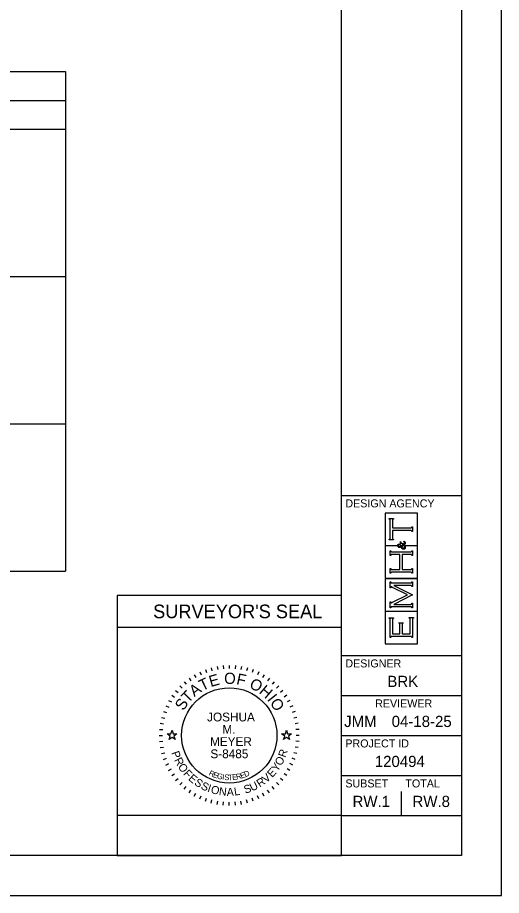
# Model space of a CAD drawing. Extents: x 0 to 34, y 0 to 22.
# Drawn here: x 27.95 to 34, y 0 to 10.97 of the extents above; entities that cross this region are included whole.
import ezdxf

# ---------------------------------------------------------------- set-up
doc = ezdxf.new("R2010")
doc.units = 0
for name, color, linetype in [('Default', 7, 'Continuous'), ('SH_Border', 7, 'Continuous'), ('SH_Cut_Line', 7, 'Continuous'), ('SH_Data', 7, 'Continuous')]:
    doc.layers.add(name, color=color, linetype=linetype)

msp = doc.modelspace()

# ---------------------------------------------------------------- linework, layer by layer
at = {"layer": 'Default'}
for points in [[(29.824, 2.02), (29.871, 2.02), (29.885, 2.065), (29.899, 2.02), (29.946, 2.02), (29.908, 1.992), (29.923, 1.948), (29.885, 1.975), (29.847, 1.948), (29.862, 1.992)], [(31.254, 2.02), (31.301, 2.02), (31.315, 2.065), (31.329, 2.02), (31.376, 2.02), (31.338, 1.992), (31.353, 1.948), (31.315, 1.975), (31.277, 1.948), (31.292, 1.992)]]:
    msp.add_lwpolyline(points, close=True, dxfattribs=at)
at = {"layer": 'SH_Border'}
for p, q in [((32, 0.5), (32, 21.5)), ((32, 5), (33.5, 5)), ((32, 3), (33.5, 3)), ((32, 2.5), (33.5, 2.5)), ((32, 2), (33.5, 2)), ((32, 1.5), (33.5, 1.5)), ((32, 1), (33.5, 1))]:
    msp.add_line(p, q, dxfattribs=at)
msp.add_lwpolyline([(1.5, 21.5), (33.5, 21.5), (33.5, 0.5), (1.5, 0.5)], close=True, dxfattribs=at)
at = {"layer": 'SH_Cut_Line'}
msp.add_lwpolyline([(0, 0), (34, 0), (34, 22), (0, 22)], close=True, dxfattribs=at)
at = {"layer": 'SH_Data'}
for p, q in [((16.868, 10.297), (28.553, 10.297)), ((28.553, 10.297), (28.553, 4.053)), ((16.868, 9.937), (28.553, 9.937)), ((16.868, 9.577), (28.553, 9.577)), ((16.868, 7.736), (28.553, 7.736)), ((16.868, 5.894), (28.553, 5.894)), ((32.952, 4.779), (32.547, 4.779)), ((32.547, 4.779), (32.547, 4.375)), ((32.952, 4.375), (32.952, 4.779)), ((32.598, 4.704), (32.598, 4.711)), ((32.598, 4.711), (32.65, 4.711)), ((32.603, 4.703), (32.598, 4.704)), ((32.606, 4.701), (32.603, 4.703)), ((32.608, 4.699), (32.606, 4.701)), ((32.61, 4.696), (32.608, 4.699)), ((32.611, 4.692), (32.61, 4.696)), ((32.611, 4.687), (32.611, 4.692)), ((32.611, 4.468), (32.611, 4.687)), ((32.638, 4.696), (32.637, 4.692)), ((32.637, 4.692), (32.637, 4.687)), ((32.637, 4.687), (32.637, 4.593)), ((32.64, 4.699), (32.638, 4.696)), ((32.642, 4.701), (32.64, 4.699)), ((32.645, 4.703), (32.642, 4.701)), ((32.65, 4.704), (32.645, 4.703)), ((32.65, 4.711), (32.65, 4.704)), ((32.637, 4.593), (32.864, 4.593)), ((32.864, 4.561), (32.637, 4.561)), ((32.637, 4.561), (32.637, 4.468)), ((32.864, 4.593), (32.869, 4.593)), ((32.87, 4.561), (32.864, 4.561)), ((32.869, 4.593), (32.873, 4.594)), ((32.874, 4.56), (32.87, 4.561)), ((32.873, 4.594), (32.876, 4.596)), ((32.876, 4.559), (32.874, 4.56)), ((32.876, 4.596), (32.878, 4.597)), ((32.878, 4.557), (32.876, 4.559)), ((32.878, 4.597), (32.88, 4.601)), ((32.88, 4.553), (32.878, 4.557)), ((32.88, 4.601), (32.881, 4.606)), ((32.881, 4.548), (32.88, 4.553)), ((32.881, 4.606), (32.888, 4.606)), ((32.888, 4.548), (32.881, 4.548)), ((32.888, 4.606), (32.888, 4.548)), ((32.598, 4.45), (32.603, 4.451)), ((32.598, 4.444), (32.598, 4.45)), ((32.65, 4.444), (32.598, 4.444)), ((32.603, 4.451), (32.606, 4.453)), ((32.606, 4.453), (32.608, 4.455)), ((32.608, 4.455), (32.61, 4.458)), ((32.61, 4.458), (32.611, 4.462)), ((32.611, 4.462), (32.611, 4.468)), ((32.637, 4.468), (32.637, 4.462)), ((32.637, 4.462), (32.638, 4.458)), ((32.638, 4.458), (32.64, 4.455)), ((32.64, 4.455), (32.642, 4.453)), ((32.642, 4.453), (32.645, 4.451)), ((32.645, 4.451), (32.65, 4.45)), ((32.65, 4.45), (32.65, 4.444)), ((32.708, 4.387), (32.711, 4.39)), ((32.711, 4.39), (32.715, 4.392)), ((32.715, 4.392), (32.72, 4.392)), ((32.72, 4.392), (32.725, 4.392)), ((32.725, 4.392), (32.729, 4.39)), ((32.729, 4.39), (32.732, 4.387)), ((32.738, 4.393), (32.738, 4.422)), ((32.738, 4.422), (32.741, 4.422)), ((32.741, 4.393), (32.738, 4.393)), ((32.741, 4.422), (32.741, 4.418)), ((32.741, 4.418), (32.742, 4.415)), ((32.742, 4.396), (32.741, 4.395)), ((32.741, 4.395), (32.741, 4.393)), ((32.742, 4.415), (32.743, 4.413)), ((32.743, 4.397), (32.742, 4.396)), ((32.743, 4.413), (32.745, 4.411)), ((32.745, 4.399), (32.743, 4.397)), ((32.745, 4.411), (32.749, 4.408)), ((32.746, 4.399), (32.745, 4.399)), ((32.748, 4.399), (32.746, 4.399)), ((32.755, 4.399), (32.748, 4.399)), ((32.749, 4.408), (32.756, 4.404)), ((32.763, 4.395), (32.755, 4.399)), ((32.756, 4.404), (32.763, 4.4)), ((32.763, 4.4), (32.77, 4.396)), ((32.772, 4.387), (32.763, 4.395)), ((32.77, 4.396), (32.776, 4.391)), ((32.776, 4.391), (32.781, 4.395)), ((32.779, 4.423), (32.781, 4.426)), ((32.782, 4.422), (32.779, 4.423)), ((32.781, 4.426), (32.787, 4.424)), ((32.781, 4.395), (32.784, 4.398)), ((32.785, 4.421), (32.782, 4.422)), ((32.784, 4.398), (32.786, 4.401)), ((32.786, 4.419), (32.785, 4.421)), ((32.788, 4.417), (32.786, 4.419)), ((32.786, 4.401), (32.788, 4.404)), ((32.787, 4.424), (32.792, 4.421)), ((32.789, 4.414), (32.788, 4.417)), ((32.788, 4.404), (32.789, 4.408)), ((32.789, 4.411), (32.789, 4.414)), ((32.789, 4.408), (32.789, 4.411)), ((32.794, 4.39), (32.791, 4.386)), ((32.792, 4.421), (32.795, 4.418)), ((32.796, 4.394), (32.794, 4.39)), ((32.795, 4.418), (32.798, 4.414)), ((32.798, 4.397), (32.796, 4.394)), ((32.798, 4.414), (32.799, 4.41)), ((32.799, 4.401), (32.798, 4.397)), ((32.799, 4.41), (32.799, 4.405)), ((32.799, 4.405), (32.799, 4.401)), ((32.547, 4.375), (32.696, 4.375)), ((32.696, 4.369), (32.547, 4.369)), ((32.547, 4.369), (32.547, 3.965)), ((32.611, 4.249), (32.611, 4.307)), ((32.611, 4.307), (32.617, 4.307)), ((32.617, 4.307), (32.619, 4.302)), ((32.619, 4.302), (32.62, 4.298)), ((32.62, 4.298), (32.623, 4.297)), ((32.623, 4.297), (32.625, 4.295)), ((32.625, 4.295), (32.629, 4.294)), ((32.629, 4.294), (32.635, 4.294)), ((32.635, 4.294), (32.864, 4.294)), ((32.696, 4.375), (32.696, 4.369)), ((32.703, 4.379), (32.705, 4.383)), ((32.703, 4.373), (32.703, 4.379)), ((32.703, 4.368), (32.703, 4.373)), ((32.705, 4.363), (32.703, 4.368)), ((32.705, 4.383), (32.708, 4.387)), ((32.708, 4.358), (32.705, 4.363)), ((32.709, 4.379), (32.708, 4.376)), ((32.708, 4.376), (32.708, 4.373)), ((32.708, 4.373), (32.708, 4.369)), ((32.708, 4.369), (32.71, 4.366)), ((32.712, 4.353), (32.708, 4.358)), ((32.712, 4.381), (32.709, 4.379)), ((32.71, 4.366), (32.712, 4.364)), ((32.714, 4.383), (32.712, 4.381)), ((32.712, 4.364), (32.715, 4.362)), ((32.718, 4.35), (32.712, 4.353)), ((32.716, 4.384), (32.714, 4.383)), ((32.715, 4.362), (32.718, 4.361)), ((32.72, 4.384), (32.716, 4.384)), ((32.718, 4.361), (32.721, 4.361)), ((32.726, 4.35), (32.718, 4.35)), ((32.724, 4.384), (32.72, 4.384)), ((32.721, 4.361), (32.723, 4.361)), ((32.723, 4.361), (32.725, 4.362)), ((32.728, 4.382), (32.724, 4.384)), ((32.725, 4.362), (32.728, 4.362)), ((32.729, 4.35), (32.726, 4.35)), ((32.731, 4.38), (32.728, 4.382)), ((32.728, 4.362), (32.731, 4.363)), ((32.731, 4.35), (32.729, 4.35)), ((32.734, 4.377), (32.731, 4.38)), ((32.731, 4.363), (32.735, 4.365)), ((32.734, 4.351), (32.731, 4.35)), ((32.732, 4.387), (32.736, 4.383)), ((32.737, 4.372), (32.734, 4.377)), ((32.737, 4.352), (32.734, 4.351)), ((32.735, 4.365), (32.74, 4.367)), ((32.736, 4.383), (32.74, 4.378)), ((32.74, 4.367), (32.737, 4.372)), ((32.741, 4.353), (32.737, 4.352)), ((32.74, 4.378), (32.744, 4.369)), ((32.746, 4.355), (32.741, 4.353)), ((32.744, 4.369), (32.754, 4.375)), ((32.752, 4.344), (32.746, 4.355)), ((32.756, 4.36), (32.751, 4.357)), ((32.751, 4.357), (32.754, 4.352)), ((32.757, 4.337), (32.752, 4.344)), ((32.754, 4.375), (32.764, 4.381)), ((32.754, 4.352), (32.757, 4.348)), ((32.761, 4.363), (32.756, 4.36)), ((32.757, 4.348), (32.761, 4.345)), ((32.763, 4.333), (32.757, 4.337)), ((32.764, 4.365), (32.761, 4.363)), ((32.761, 4.345), (32.765, 4.343)), ((32.768, 4.329), (32.763, 4.333)), ((32.764, 4.381), (32.772, 4.387)), ((32.768, 4.367), (32.764, 4.365)), ((32.765, 4.343), (32.769, 4.341)), ((32.774, 4.372), (32.768, 4.367)), ((32.774, 4.327), (32.768, 4.329)), ((32.769, 4.341), (32.773, 4.341)), ((32.773, 4.341), (32.778, 4.341)), ((32.782, 4.378), (32.774, 4.372)), ((32.779, 4.327), (32.774, 4.327)), ((32.778, 4.341), (32.782, 4.343)), ((32.785, 4.327), (32.779, 4.327)), ((32.786, 4.373), (32.782, 4.378)), ((32.782, 4.343), (32.786, 4.346)), ((32.79, 4.329), (32.785, 4.327)), ((32.791, 4.386), (32.786, 4.381)), ((32.786, 4.381), (32.791, 4.376)), ((32.788, 4.369), (32.786, 4.373)), ((32.786, 4.346), (32.789, 4.349)), ((32.79, 4.367), (32.788, 4.369)), ((32.789, 4.349), (32.791, 4.353)), ((32.791, 4.364), (32.79, 4.367)), ((32.793, 4.334), (32.79, 4.329)), ((32.791, 4.376), (32.795, 4.37)), ((32.791, 4.361), (32.791, 4.364)), ((32.791, 4.359), (32.791, 4.361)), ((32.791, 4.353), (32.791, 4.359)), ((32.797, 4.338), (32.793, 4.334)), ((32.795, 4.37), (32.797, 4.366)), ((32.797, 4.366), (32.798, 4.361)), ((32.799, 4.344), (32.797, 4.338)), ((32.798, 4.361), (32.799, 4.357)), ((32.803, 4.369), (32.799, 4.375)), ((32.799, 4.375), (32.952, 4.375)), ((32.799, 4.357), (32.799, 4.352)), ((32.799, 4.352), (32.799, 4.344)), ((32.952, 4.369), (32.803, 4.369)), ((32.864, 4.294), (32.869, 4.294)), ((32.869, 4.294), (32.873, 4.295)), ((32.873, 4.295), (32.876, 4.297)), ((32.876, 4.297), (32.878, 4.298)), ((32.878, 4.298), (32.88, 4.302)), ((32.88, 4.302), (32.881, 4.307)), ((32.881, 4.307), (32.888, 4.307)), ((32.888, 4.307), (32.888, 4.249)), ((32.952, 3.965), (32.952, 4.369)), ((32.617, 4.249), (32.611, 4.249)), ((32.618, 4.254), (32.617, 4.249)), ((32.62, 4.258), (32.618, 4.254)), ((32.623, 4.26), (32.62, 4.258)), ((32.625, 4.261), (32.623, 4.26)), ((32.629, 4.262), (32.625, 4.261)), ((32.635, 4.262), (32.629, 4.262)), ((32.732, 4.262), (32.635, 4.262)), ((32.732, 4.072), (32.732, 4.262)), ((32.864, 4.262), (32.759, 4.262)), ((32.759, 4.262), (32.759, 4.072)), ((32.87, 4.262), (32.864, 4.262)), ((32.874, 4.261), (32.87, 4.262)), ((32.876, 4.26), (32.874, 4.261)), ((32.878, 4.258), (32.876, 4.26)), ((32.88, 4.254), (32.878, 4.258)), ((32.881, 4.249), (32.88, 4.254)), ((32.888, 4.249), (32.881, 4.249)), ((32.611, 4.027), (32.611, 4.085)), ((32.611, 4.085), (32.617, 4.085)), ((32.617, 4.085), (32.619, 4.08)), ((32.619, 4.08), (32.62, 4.076)), ((32.62, 4.076), (32.623, 4.074)), ((32.623, 4.074), (32.625, 4.073)), ((32.625, 4.073), (32.629, 4.072)), ((32.629, 4.072), (32.635, 4.072)), ((32.635, 4.072), (32.732, 4.072)), ((32.759, 4.072), (32.864, 4.072)), ((32.864, 4.072), (32.87, 4.072)), ((32.87, 4.072), (32.874, 4.073)), ((32.874, 4.073), (32.876, 4.074)), ((32.876, 4.074), (32.878, 4.076)), ((32.878, 4.076), (32.88, 4.08)), ((32.88, 4.08), (32.881, 4.085)), ((32.881, 4.085), (32.888, 4.085)), ((32.888, 4.085), (32.888, 4.027)), ((16.868, 4.053), (28.553, 4.053)), ((32.547, 3.965), (32.952, 3.965)), ((32.952, 3.959), (32.547, 3.959)), ((32.547, 3.959), (32.547, 3.555)), ((32.617, 4.027), (32.611, 4.027)), ((32.618, 4.032), (32.617, 4.027)), ((32.62, 4.036), (32.618, 4.032)), ((32.623, 4.037), (32.62, 4.036)), ((32.625, 4.039), (32.623, 4.037)), ((32.629, 4.04), (32.625, 4.039)), ((32.635, 4.04), (32.629, 4.04)), ((32.864, 4.04), (32.635, 4.04)), ((32.75, 4), (32.75, 4)), ((32.87, 4.04), (32.864, 4.04)), ((32.874, 4.039), (32.87, 4.04)), ((32.876, 4.038), (32.874, 4.039)), ((32.878, 4.036), (32.876, 4.038)), ((32.88, 4.032), (32.878, 4.036)), ((32.881, 4.027), (32.88, 4.032)), ((32.888, 4.027), (32.881, 4.027)), ((32.952, 3.555), (32.952, 3.959)), ((32.611, 3.845), (32.611, 3.918)), ((32.611, 3.918), (32.617, 3.918)), ((32.617, 3.845), (32.611, 3.845)), ((32.617, 3.918), (32.619, 3.912)), ((32.62, 3.852), (32.617, 3.845)), ((32.619, 3.912), (32.62, 3.909)), ((32.62, 3.909), (32.623, 3.907)), ((32.622, 3.855), (32.62, 3.852)), ((32.626, 3.855), (32.622, 3.855)), ((32.623, 3.907), (32.625, 3.905)), ((32.625, 3.905), (32.629, 3.905)), ((32.629, 3.855), (32.626, 3.855)), ((32.629, 3.905), (32.635, 3.905)), ((32.633, 3.853), (32.629, 3.855)), ((32.64, 3.85), (32.633, 3.853)), ((32.635, 3.905), (32.864, 3.905)), ((32.825, 3.757), (32.64, 3.85)), ((32.864, 3.873), (32.654, 3.873)), ((32.654, 3.873), (32.888, 3.755)), ((32.864, 3.905), (32.869, 3.905)), ((32.87, 3.873), (32.864, 3.873)), ((32.869, 3.905), (32.873, 3.905)), ((32.874, 3.872), (32.87, 3.873)), ((32.873, 3.905), (32.876, 3.907)), ((32.876, 3.87), (32.874, 3.872)), ((32.876, 3.907), (32.878, 3.909)), ((32.878, 3.869), (32.876, 3.87)), ((32.878, 3.909), (32.88, 3.912)), ((32.88, 3.865), (32.878, 3.869)), ((32.88, 3.912), (32.881, 3.918)), ((32.881, 3.86), (32.88, 3.865)), ((32.881, 3.918), (32.888, 3.918)), ((32.888, 3.86), (32.881, 3.86)), ((32.888, 3.918), (32.888, 3.86)), ((32, 3.75), (29.2, 3.75)), ((29.2, 3.75), (29.2, 0.5)), ((32, 0.5), (32, 3.75)), ((32.641, 3.665), (32.825, 3.757)), ((32.888, 3.755), (32.654, 3.638)), ((32.611, 3.596), (32.611, 3.668)), ((32.611, 3.668), (32.617, 3.668)), ((32.617, 3.668), (32.62, 3.662)), ((32.62, 3.662), (32.622, 3.658)), ((32.622, 3.658), (32.626, 3.658)), ((32.626, 3.658), (32.627, 3.658)), ((32.627, 3.658), (32.633, 3.661)), ((32.633, 3.661), (32.641, 3.665)), ((32.654, 3.638), (32.864, 3.638)), ((32.864, 3.638), (32.869, 3.638)), ((32.869, 3.638), (32.873, 3.639)), ((32.873, 3.639), (32.876, 3.641)), ((32.876, 3.641), (32.878, 3.643)), ((32.878, 3.643), (32.88, 3.646)), ((32.88, 3.646), (32.881, 3.651)), ((32.881, 3.651), (32.888, 3.651)), ((32.888, 3.651), (32.888, 3.596)), ((32.547, 3.555), (32.952, 3.555)), ((32.952, 3.549), (32.547, 3.549)), ((32.547, 3.549), (32.547, 3.145)), ((32.617, 3.596), (32.611, 3.596)), ((32.618, 3.602), (32.617, 3.596)), ((32.62, 3.605), (32.618, 3.602)), ((32.623, 3.607), (32.62, 3.605)), ((32.625, 3.609), (32.623, 3.607)), ((32.629, 3.609), (32.625, 3.609)), ((32.635, 3.609), (32.629, 3.609)), ((32.864, 3.609), (32.635, 3.609)), ((32.87, 3.609), (32.864, 3.609)), ((32.874, 3.609), (32.87, 3.609)), ((32.876, 3.607), (32.874, 3.609)), ((32.878, 3.605), (32.876, 3.607)), ((32.88, 3.602), (32.878, 3.605)), ((32.881, 3.596), (32.88, 3.602)), ((32.888, 3.596), (32.881, 3.596)), ((32.952, 3.145), (32.952, 3.549)), ((32.598, 3.462), (32.598, 3.469)), ((32.598, 3.469), (32.65, 3.469)), ((32.603, 3.461), (32.598, 3.462)), ((32.606, 3.459), (32.603, 3.461)), ((32.608, 3.457), (32.606, 3.459)), ((32.61, 3.455), (32.608, 3.457)), ((32.611, 3.451), (32.61, 3.455)), ((32.611, 3.445), (32.611, 3.451)), ((32.611, 3.225), (32.611, 3.445)), ((32.64, 3.457), (32.638, 3.455)), ((32.638, 3.455), (32.638, 3.451)), ((32.638, 3.451), (32.638, 3.445)), ((32.638, 3.445), (32.638, 3.27)), ((32.642, 3.459), (32.64, 3.457)), ((32.645, 3.461), (32.642, 3.459)), ((32.65, 3.462), (32.645, 3.461)), ((32.65, 3.469), (32.65, 3.462)), ((32.719, 3.402), (32.719, 3.408)), ((32.719, 3.408), (32.772, 3.408)), ((32.724, 3.401), (32.719, 3.402)), ((32.772, 3.402), (32.767, 3.401)), ((32.772, 3.408), (32.772, 3.402)), ((32.848, 3.465), (32.848, 3.472)), ((32.848, 3.472), (32.901, 3.472)), ((32.853, 3.464), (32.848, 3.465)), ((32.857, 3.462), (32.853, 3.464)), ((32.859, 3.46), (32.857, 3.462)), ((32.86, 3.458), (32.859, 3.46)), ((32.861, 3.453), (32.86, 3.458)), ((32.861, 3.448), (32.861, 3.453)), ((32.861, 3.27), (32.861, 3.448)), ((32.889, 3.457), (32.888, 3.453)), ((32.888, 3.453), (32.888, 3.448)), ((32.888, 3.448), (32.888, 3.225)), ((32.891, 3.46), (32.889, 3.457)), ((32.892, 3.462), (32.891, 3.46)), ((32.896, 3.464), (32.892, 3.462)), ((32.901, 3.465), (32.896, 3.464)), ((32.901, 3.472), (32.901, 3.465)), ((32, 3.35), (29.2, 3.35)), ((32.728, 3.399), (32.724, 3.401)), ((32.729, 3.396), (32.728, 3.399)), ((32.731, 3.394), (32.729, 3.396)), ((32.732, 3.39), (32.731, 3.394)), ((32.732, 3.384), (32.732, 3.39)), ((32.732, 3.27), (32.732, 3.384)), ((32.76, 3.394), (32.759, 3.39)), ((32.759, 3.39), (32.759, 3.384)), ((32.759, 3.384), (32.759, 3.27)), ((32.761, 3.396), (32.76, 3.394)), ((32.763, 3.399), (32.761, 3.396)), ((32.767, 3.401), (32.763, 3.399)), ((32.617, 3.225), (32.611, 3.225)), ((32.619, 3.23), (32.617, 3.225)), ((32.62, 3.234), (32.619, 3.23)), ((32.623, 3.235), (32.62, 3.234)), ((32.625, 3.237), (32.623, 3.235)), ((32.629, 3.238), (32.625, 3.237)), ((32.635, 3.238), (32.629, 3.238)), ((32.864, 3.238), (32.635, 3.238)), ((32.638, 3.27), (32.732, 3.27)), ((32.759, 3.27), (32.861, 3.27)), ((32.87, 3.238), (32.864, 3.238)), ((32.874, 3.237), (32.87, 3.238)), ((32.876, 3.235), (32.874, 3.237)), ((32.878, 3.234), (32.876, 3.235)), ((32.88, 3.23), (32.878, 3.234)), ((32.881, 3.225), (32.88, 3.23)), ((32.888, 3.225), (32.881, 3.225)), ((32.547, 3.145), (32.952, 3.145)), ((30.448, 2.862), (30.455, 2.822)), ((30.524, 2.872), (30.527, 2.832)), ((30.6, 2.875), (30.6, 2.835)), ((30.676, 2.872), (30.673, 2.832)), ((30.752, 2.862), (30.745, 2.822)), ((30.163, 2.758), (30.183, 2.723)), ((30.23, 2.793), (30.247, 2.757)), ((30.301, 2.822), (30.314, 2.785)), ((30.374, 2.845), (30.384, 2.807)), ((30.826, 2.845), (30.816, 2.807)), ((30.899, 2.822), (30.886, 2.785)), ((30.97, 2.793), (30.953, 2.757)), ((31.037, 2.758), (31.017, 2.723)), ((30.038, 2.67), (30.063, 2.64)), ((30.098, 2.717), (30.121, 2.684)), ((31.102, 2.717), (31.079, 2.684)), ((31.162, 2.67), (31.137, 2.64)), ((29.93, 2.562), (29.96, 2.537)), ((29.981, 2.619), (30.01, 2.59)), ((31.219, 2.619), (31.19, 2.59)), ((31.27, 2.562), (31.24, 2.537)), ((29.842, 2.438), (29.877, 2.418)), ((29.883, 2.502), (29.916, 2.479)), ((31.317, 2.502), (31.284, 2.479)), ((31.358, 2.438), (31.323, 2.418)), ((29.807, 2.37), (29.843, 2.353)), ((31.393, 2.37), (31.357, 2.353)), ((29.755, 2.226), (29.793, 2.216)), ((29.778, 2.299), (29.815, 2.286)), ((31.422, 2.299), (31.385, 2.286)), ((31.445, 2.226), (31.407, 2.216)), ((29.738, 2.152), (29.778, 2.145)), ((31.462, 2.152), (31.422, 2.145)), ((29.725, 2), (29.765, 2)), ((29.728, 2.076), (29.768, 2.073)), ((31.472, 2.076), (31.432, 2.073)), ((31.475, 2), (31.435, 2)), ((29.728, 1.924), (29.768, 1.927)), ((31.472, 1.924), (31.432, 1.927)), ((29.738, 1.848), (29.778, 1.855)), ((29.755, 1.774), (29.793, 1.784)), ((31.445, 1.774), (31.407, 1.784)), ((31.462, 1.848), (31.422, 1.855)), ((29.778, 1.701), (29.815, 1.714)), ((29.807, 1.63), (29.843, 1.647)), ((31.393, 1.63), (31.357, 1.647)), ((31.422, 1.701), (31.385, 1.714)), ((29.842, 1.563), (29.877, 1.583)), ((31.358, 1.563), (31.323, 1.583)), ((29.883, 1.498), (29.916, 1.521)), ((29.93, 1.438), (29.96, 1.463)), ((31.27, 1.438), (31.24, 1.463)), ((31.317, 1.498), (31.284, 1.521)), ((29.981, 1.381), (30.01, 1.41)), ((30.038, 1.33), (30.063, 1.36)), ((31.162, 1.33), (31.137, 1.36)), ((31.219, 1.381), (31.19, 1.41)), ((30.098, 1.283), (30.121, 1.316)), ((30.163, 1.242), (30.183, 1.277)), ((30.23, 1.207), (30.247, 1.243)), ((30.301, 1.178), (30.314, 1.215)), ((30.899, 1.178), (30.886, 1.215)), ((30.97, 1.207), (30.953, 1.243)), ((31.037, 1.242), (31.017, 1.277)), ((31.102, 1.283), (31.079, 1.316)), ((32.75, 1), (32.75, 1.3)), ((30.374, 1.155), (30.384, 1.193)), ((30.448, 1.138), (30.455, 1.178)), ((30.524, 1.128), (30.527, 1.168)), ((30.6, 1.125), (30.6, 1.165)), ((30.676, 1.128), (30.673, 1.168)), ((30.752, 1.138), (30.745, 1.178)), ((30.826, 1.155), (30.816, 1.193)), ((32, 0.5), (29.2, 0.5))]:
    msp.add_line(p, q, dxfattribs=at)
msp.add_lwpolyline([(32, 0.5), (32, 1), (29.2, 1), (29.2, 0.5)], close=True, dxfattribs=at)
msp.add_circle((30.6, 2), 0.595, dxfattribs=at)

# ---------------------------------------------------------------- texts
for s, height, p in [('DESIGN AGENCY', 0.1, (32.05, 4.85)), ("SURVEYOR'S SEAL", 0.17, (29.648, 3.465)), ('DESIGNER', 0.1, (32.05, 2.85)), ('BRK', 0.14, (32.575, 2.605)), ('REVIEWER', 0.1, (32.422, 2.35)), ('JOSHUA', 0.11, (30.323, 2.175)), ('JMM', 0.14, (32.035, 2.105)), ('04-18-25', 0.14, (32.629, 2.105)), ('M.', 0.11, (30.513, 2.022)), ('MEYER', 0.11, (30.359, 1.868)), ('PROJECT ID', 0.1, (32.05, 1.85)), ('S-8485', 0.11, (30.364, 1.715)), ('120494', 0.14, (32.418, 1.605)), ('SUBSET', 0.1, (32.05, 1.35)), ('TOTAL', 0.1, (32.8, 1.35)), ('RW.1', 0.14, (32.14, 1.105)), ('RW.8', 0.14, (32.889, 1.105))]:
    msp.add_text(s, height=height, dxfattribs=at).set_placement(p)
for s, height, rotation, p in [('E', 0.14, 15.7571, (30.368, 2.604)), ('O', 0.14, 359.7812, (30.535, 2.644)), ('F', 0.14, 347.4362, (30.681, 2.642)), ('A', 0.14, 36.4747, (30.163, 2.478)), ('T', 0.14, 25.7167, (30.262, 2.552)), ('O', 0.14, 332.2586, (30.84, 2.602)), ('H', 0.14, 319.9136, (30.963, 2.536)), ('T', 0.14, 46.4344, (30.088, 2.396)), ('S', 0.14, 57.1924, (30.028, 2.301)), ('I', 0.14, 308.367, (31.066, 2.448)), ('O', 0.14, 303.1491, (31.102, 2.409)), ('P', 0.1, 289.7431, (29.875, 1.784)), ('R', 0.1, 70.983, (31.301, 1.717)), ('R', 0.1, 296.9802, (29.909, 1.693)), ('Y', 0.1, 55.5058, (31.2, 1.54)), ('O', 0.1, 62.7428, (31.25, 1.613)), ('O', 0.1, 304.7158, (29.953, 1.608)), ('F', 0.1, 312.956, (30.019, 1.516)), ('R', 0.07, 334.487, (30.337, 1.505)), ('E', 0.07, 341.04, (30.391, 1.48)), ('E', 0.07, 17.6836, (30.75, 1.46)), ('D', 0.07, 23.3052, (30.801, 1.477)), ('E', 0.1, 48.2687, (31.137, 1.467)), ('E', 0.1, 319.6885, (30.081, 1.45)), ('S', 0.1, 326.9255, (30.155, 1.389)), ('G', 0.07, 347.4752, (30.441, 1.462)), ('I', 0.07, 353.7858, (30.509, 1.447)), ('S', 0.07, 356.8926, (30.536, 1.443)), ('T', 0.07, 3.0061, (30.586, 1.439)), ('E', 0.07, 6.0117, (30.639, 1.441)), ('R', 0.07, 11.9184, (30.692, 1.447)), ('R', 0.1, 33.296, (30.981, 1.347)), ('V', 0.1, 41.0316, (31.061, 1.401)), ('S', 0.1, 334.1626, (30.236, 1.337)), ('I', 0.1, 341.3997, (30.319, 1.298)), ('O', 0.1, 345.1351, (30.362, 1.282)), ('N', 0.1, 353.3752, (30.466, 1.255)), ('A', 0.1, 1.1108, (30.569, 1.244)), ('L', 0.1, 8.3479, (30.666, 1.247)), ('S', 0.1, 18.3234, (30.8, 1.271)), ('U', 0.1, 25.5604, (30.883, 1.299))]:
    msp.add_text(s, height=height, rotation=rotation, dxfattribs=at).set_placement(p)

doc.saveas('drawing.dxf')
